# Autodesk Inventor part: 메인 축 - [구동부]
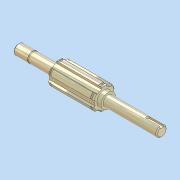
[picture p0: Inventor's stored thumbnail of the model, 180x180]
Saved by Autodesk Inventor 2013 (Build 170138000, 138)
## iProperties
Company: 한국ATC센터
Created: 2014-07
Part Number: 메인 축 - [구동부]
Document SubType Name: 모델링
Designer: KYOUNG IL JANG
Mass: 168.566 g
Surface Area: 72.5104 cm^2
Volume: 21.4461 cm^3
Density: 7.86 g/cm^3
Material: 강철, 연강
변환 표준: STEP AP214IS
파일 이름: C:\Users\SeoGD\Desktop\?쒗뿕\硫붿씤 異?.stp
전처리기: Build: 253, Release: 2010 SP1 - Date: Wed 07/29/2009
전송 단위: 밀리미터
불확실성: 0.01
Author: KYOUNG IL JANG
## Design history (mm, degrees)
sketch "스케치1"
  geometry: L1 (-69.5, 0)-(69.5, 0); L2 (69.5, 0)-(69.5, 5); L3 (69.5, 5)-(55.5, 5); L4 (55.5, 5)-(55.5, 4.8); L5 (55.5, 4.8)-(54.35, 4.8); L6 (54.35, 4.8)-(54.35, 5); L7 (54.35, 5)-(30.5, 5); L8 (30.5, 5)-(30.5, 9); L9 (30.5, 9)-(-13.5, 9); L10 (-13.5, 9)-(-13.5, 7); L11 (-13.5, 7)-(-17.5, 7); L12 (-17.5, 7)-(-17.5, 5); L13 (-17.5, 5)-(-69.5, 5); L14 (-69.5, 5)-(-69.5, 0); 2 further points
  constraints: 28 end point, 9 parallel, 4 collinear, 2 perpendicular, 1 coincident, 1 horizontal, 1 midpoint
  dimensions: "d2" = 1.15 distance between parallel lines of L6 L4; "d3" = 10 diameter of L3 L1; "d4" = 9.6 diameter of L5 L1; "d6" = 44 distance between parallel lines of L10 L8; "d7" = 4 distance between parallel lines of L12 L10; "d8" = 14 diameter of L11 L1; "d9" = 18 diameter of L9 L1; "d33" = 52 distance from line of L12.end L14; "d37" = 39 distance between parallel lines of L8 L2; "d38" = 14 distance between parallel lines of L2 L4
revolve "회전1" sketch "스케치1" stored, may be unused: angle "d10" = 90 deg
sketch "스케치2"
  geometry: L1 (2.5, 10.712)-(2.5, 8.646); L2 (-2.5, 10.712)-(-2.5, 8.646); A1 r 9 centre (0, 0) between (2.5, 8.646) and (-2.5, 8.646) reference; A2 r 11 centre (0, 0) between (2.5, 10.712) and (-2.5, 10.712); 1 further point
  constraints: 4 end point, 4 point on circle, 2 parallel, 1 centre point, 1 coincident, 1 vertical
  dimensions: "d11" = 22 diameter of A2; "d12" = 5 distance between parallel lines of L1 L2
extrude "돌출1" join sketch "스케치2" stored distance "d13" = 10; taper "d14" = 0 deg
chamfer "모따기1" distance "d15" = 1; stored, may be unused: second distance "d16" = 2, angle "d17" = 45 deg
node "작업 평면1"
node "작업 평면2"
sketch "스케치3"
  geometry: L1 (2.5, 10.712)-(2.5, 10.198); L2 (-2.5, 10.712)-(-2.5, 10.198); A1 r 11 centre (0, 0) between (2.5, 10.712) and (-2.5, 10.712) reference; A2 r 10.5 centre (0, 0) between (2.5, 10.198) and (-2.5, 10.198); 1 further point
  constraints: 4 end point, 2 point on circle, 1 centre point, 1 coincident, 1 parallel, 1 vertical
  dimensions: "d19" = 21 diameter of A2
extrude "돌출2" cut sketch "스케치3" distance "d20" = 1.35; taper "d21" = 0 deg
node "작업 평면3"
sketch "스케치4"
  geometry: L1 (-26, -5)-(-26, 5) reference; L2 (-26, 1.5)-(-12.5, 1.5); L3 (-12.5, -1.5)-(-26, -1.5); A1 r 1.5 centre (-12.5, 0) between (-12.5, -1.5) and (-12.5, 1.5); 2 further points
  constraints: 4 end point, 2 perpendicular, 2 point on circle, 2 point on line, 2 tangent, 1 centre point, 1 horizontal alignment, 1 midpoint
  dimensions: "d25" = 3 distance between parallel lines of L3 L2; "d26" = 15 dimension on A1 L1
extrude "돌출3" cut sketch "스케치4" distance "d27" = 1.8; taper "d28" = 0 deg
chamfer "모따기2" distance "d29" = 1; stored, may be unused: second distance "d30" = 2, angle "d31" = 45 deg
node "솔리드1"
node "솔리드 본체"
node "곡면 본체"
mirror "대칭1"
pattern_circular "원형 패턴1" dims "d23" = 360 deg
node "솔리드2"
other parameters: "d18" = -1.65
